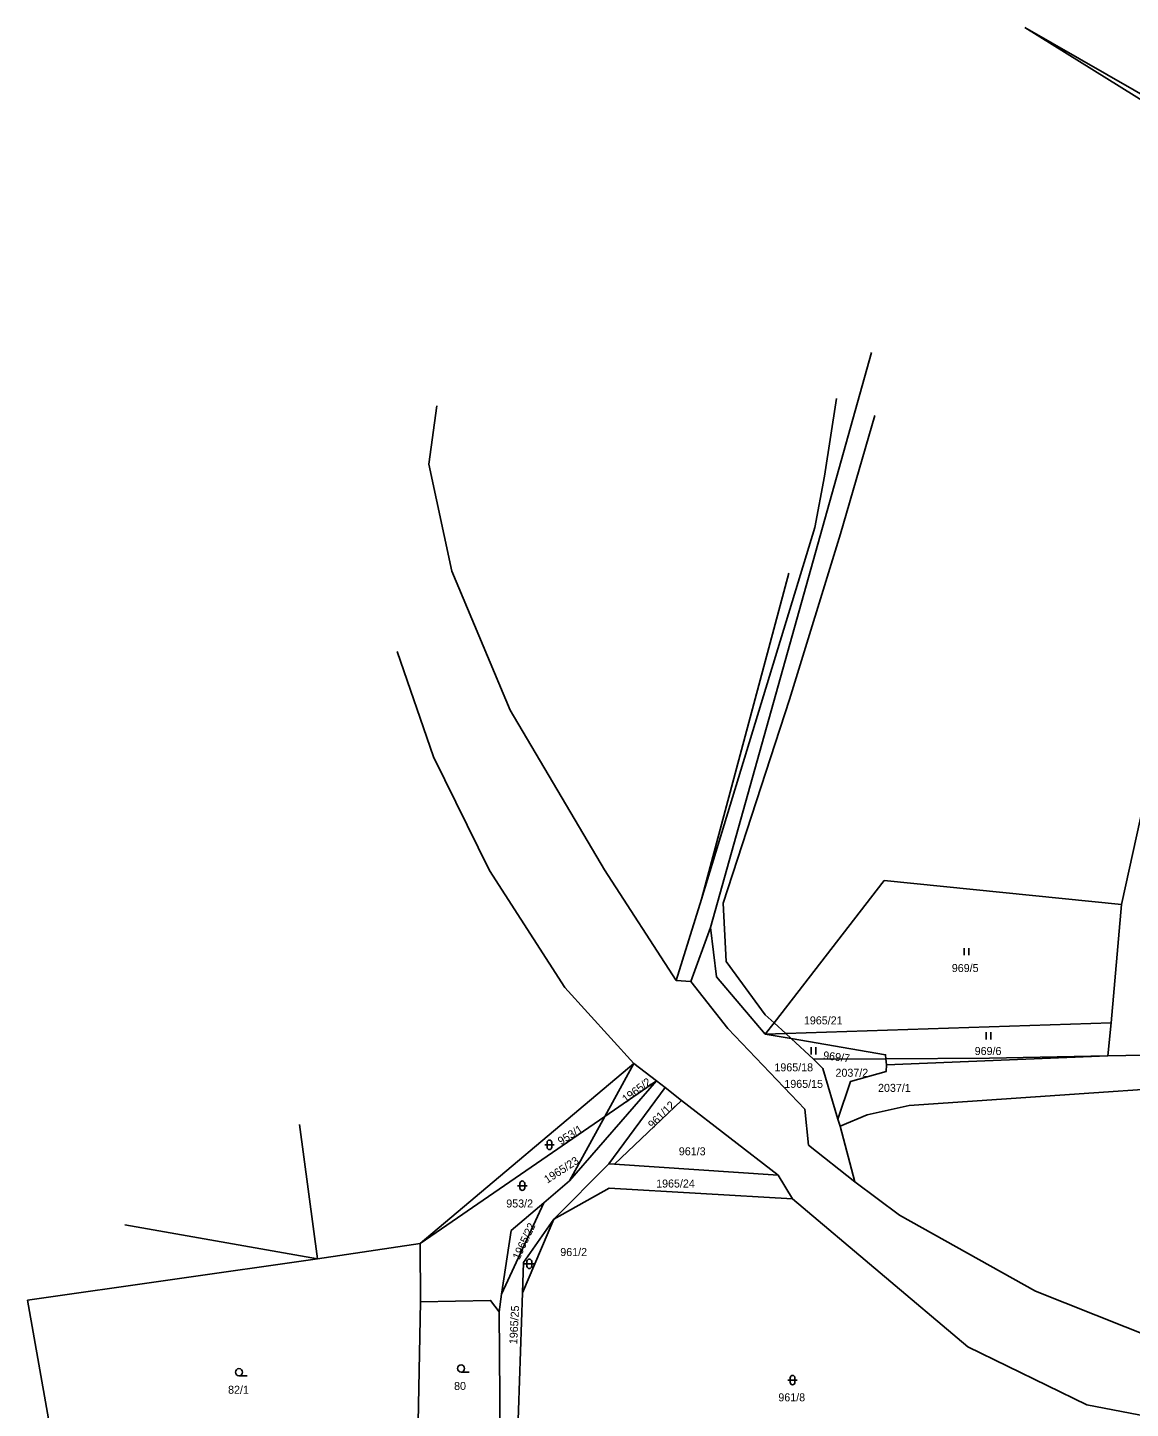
# Model space of a CAD drawing. Extents: x -794765 to -785424, y -1118958 to -1108731.
# Drawn here: x -788214.6 to -787980.3, y -1116299.9 to -1116006.6 of the extents above; entities that cross this region are included whole.
import ezdxf

# ---------------------------------------------------------------- set-up
doc = ezdxf.new("R2010")
doc.units = 0
for name, color, linetype in [('Level 66', 7, 'Continuous'), ('Level 75', 7, 'Continuous'), ('Level 76', 7, 'Continuous')]:
    doc.layers.add(name, color=color, linetype=linetype)

msp = doc.modelspace()

# ---------------------------------------------------------------- linework, layer by layer
at = {"layer": 'Level 66'}
for p, q in [((-788015.63, -1116203.58), (-788015.63, -1116202.08)), ((-788014.63, -1116203.58), (-788014.63, -1116202.08)), ((-788010.9, -1116221.48), (-788010.9, -1116219.98)), ((-788009.9, -1116221.48), (-788009.9, -1116219.98)), ((-788048.11, -1116224.67), (-788048.11, -1116223.17)), ((-788047.11, -1116224.67), (-788047.11, -1116223.17)), ((-788104.72, -1116243.88), (-788102.72, -1116243.88)), ((-788104.22, -1116243.38), (-788104.22, -1116244.38)), ((-788103.22, -1116244.38), (-788103.22, -1116243.38)), ((-788110.49, -1116252.56), (-788108.49, -1116252.56)), ((-788109.99, -1116252.06), (-788109.99, -1116253.06)), ((-788108.99, -1116253.06), (-788108.99, -1116252.06)), ((-788109, -1116269.16), (-788107, -1116269.16)), ((-788108.5, -1116268.66), (-788108.5, -1116269.66)), ((-788107.5, -1116269.66), (-788107.5, -1116268.66)), ((-788122.51, -1116292.13), (-788120.76, -1116292.13)), ((-788169.7, -1116292.92), (-788167.95, -1116292.92)), ((-788053.07, -1116293.84), (-788051.07, -1116293.84)), ((-788052.57, -1116293.34), (-788052.57, -1116294.34)), ((-788051.57, -1116294.34), (-788051.57, -1116293.34))]:
    msp.add_line(p, q, dxfattribs=at)
for centre in [(-788169.7, -1116292.17), (-788122.51, -1116291.38)]:
    msp.add_circle(centre, 0.75, dxfattribs=at)
for centre, start, end in [((-788103.72, -1116243.38), 0, 180), ((-788103.72, -1116244.38), 180, 359.9879), ((-788109.49, -1116252.06), 0, 180), ((-788109.49, -1116253.06), 180, 359.9879), ((-788108, -1116268.66), 0, 180), ((-788108, -1116269.66), 180, 359.9879), ((-788052.07, -1116293.34), 0, 180), ((-788052.07, -1116294.34), 180, 359.9879)]:
    msp.add_arc(centre, 0.5, start, end, dxfattribs=at)
at = {"layer": 'Level 75'}
for p, q in [((-788002.71, -1116006.59), (-787882.08, -1116075.64)), ((-788002.71, -1116006.59), (-787888.56, -1116077.57)), ((-788035.27, -1116075.57), (-788069.53, -1116197.7)), ((-788052.85, -1116122.43), (-788071.41, -1116191.68)), ((-788076.78, -1116209), (-788071.41, -1116191.68)), ((-787982.18, -1116192.85), (-787984.36, -1116217.96)), ((-788069.53, -1116197.7), (-788073.71, -1116209.17)), ((-788073.71, -1116209.17), (-788076.78, -1116209)), ((-788057.85, -1116220.39), (-788055.99, -1116217.98)), ((-788055.99, -1116217.98), (-788053.51, -1116220.25)), ((-788053.51, -1116220.25), (-787984.36, -1116217.96)), ((-787984.36, -1116217.96), (-787985.07, -1116224.98)), ((-788053.51, -1116220.25), (-788057.85, -1116220.39)), ((-788052.33, -1116221.33), (-788057.85, -1116220.39)), ((-788053.51, -1116220.25), (-788052.33, -1116221.33)), ((-788052.33, -1116221.33), (-788047.6, -1116225.66)), ((-788032.12, -1116226.88), (-787985.07, -1116224.98)), ((-787985.07, -1116224.98), (-787960.83, -1116224.48)), ((-788131.17, -1116264.83), (-788085.81, -1116226.64)), ((-788085.81, -1116226.64), (-788091.96, -1116237.85)), ((-788080.98, -1116230.3), (-788085.81, -1116226.64)), ((-788047.6, -1116225.66), (-788032.22, -1116225.59)), ((-788032.22, -1116225.59), (-788032.12, -1116226.88)), ((-788099.45, -1116251.52), (-788080.98, -1116230.3)), ((-788091.96, -1116237.85), (-788080.98, -1116230.3)), ((-788080.98, -1116230.3), (-788079.1, -1116231.73)), ((-788079.1, -1116231.73), (-788091.13, -1116247.9)), ((-788079.1, -1116231.73), (-788075.63, -1116234.43)), ((-788075.63, -1116234.43), (-788089.89, -1116247.98)), ((-788055.15, -1116250.34), (-788075.63, -1116234.43)), ((-788153.05, -1116268.07), (-788156.81, -1116239.54)), ((-788131.17, -1116264.83), (-788091.96, -1116237.85)), ((-788099.45, -1116251.52), (-788091.96, -1116237.85)), ((-788041.98, -1116239.94), (-788042.43, -1116238.43)), ((-788041.98, -1116239.94), (-788038.84, -1116251.72)), ((-788102.81, -1116259.69), (-788091.13, -1116247.9)), ((-788091.13, -1116247.9), (-788089.89, -1116247.98)), ((-788089.89, -1116247.98), (-788055.15, -1116250.34)), ((-788104.94, -1116256.19), (-788099.45, -1116251.52)), ((-788055.15, -1116250.34), (-788052.1, -1116255.33)), ((-788113.88, -1116275.59), (-788104.94, -1116256.19)), ((-788109.43, -1116275.32), (-788102.81, -1116259.69)), ((-788193.99, -1116260.86), (-788153.05, -1116268.07)), ((-788153.05, -1116268.07), (-788131.17, -1116264.83)), ((-788131.17, -1116264.83), (-788131.16, -1116277.26)), ((-788153.05, -1116268.07), (-788214.62, -1116276.87)), ((-788214.62, -1116276.87), (-788207.41, -1116317.68)), ((-788131.16, -1116277.26), (-788131.71, -1116307.69)), ((-788114.43, -1116279.33), (-788113.88, -1116275.59)), ((-788109.43, -1116275.32), (-788110.98, -1116320.69)), ((-788114.43, -1116279.33), (-788114.17, -1116310.48))]:
    msp.add_line(p, q, dxfattribs=at)
for points in [[(-788076.78, -1116209), (-788092, -1116185.5), (-788112.04, -1116151.55), (-788124.45, -1116122.06), (-788129.39, -1116099.34), (-788127.68, -1116086.93)], [(-788071.41, -1116191.68), (-788047.32, -1116112.79), (-788045.26, -1116101.88), (-788042.7, -1116085.39)], [(-788034.6, -1116088.94), (-788041.84, -1116114.12), (-788052.73, -1116149.32), (-788066.81, -1116192.53), (-788066.19, -1116204.97), (-788057.87, -1116216.25), (-788055.99, -1116217.98)], [(-788136.07, -1116139.09), (-788128.33, -1116161.49), (-788116.43, -1116185.63), (-788100.46, -1116210.48), (-788085.81, -1116226.64)], [(-787961.82, -1116139.28), (-787975, -1116160.37), (-787982.18, -1116192.85)], [(-787982.18, -1116192.85), (-788032.59, -1116187.72), (-788055.99, -1116217.98)], [(-788057.85, -1116220.39), (-788068.21, -1116208.21), (-788069.53, -1116197.7)], [(-788038.84, -1116251.72), (-788048.68, -1116243.92), (-788049.47, -1116236.31), (-788065.84, -1116219.2), (-788073.71, -1116209.17)], [(-788052.33, -1116221.33), (-788032.28, -1116224.75), (-788032.22, -1116225.59)], [(-788032.22, -1116225.59), (-788010.21, -1116225.5), (-787985.07, -1116224.98)], [(-788042.43, -1116238.43), (-788045.64, -1116227.68), (-788047.6, -1116225.66)], [(-788042.43, -1116238.43), (-788039.74, -1116230.4), (-788032.19, -1116228.31), (-788032.12, -1116226.88)], [(-787888.24, -1116227.49), (-787936.38, -1116229.33), (-788027.3, -1116235.54), (-788036.22, -1116237.52), (-788041.98, -1116239.94)], [(-788052.1, -1116255.33), (-788091.02, -1116253.11), (-788102.81, -1116259.69)], [(-787853.4, -1116319.28), (-787937.67, -1116297.07), (-787968.58, -1116287.61), (-788000.45, -1116274.98), (-788029.34, -1116258.85), (-788038.84, -1116251.72)], [(-788113.88, -1116275.59), (-788111.89, -1116262.1), (-788104.94, -1116256.19)], [(-788052.1, -1116255.33), (-788014.79, -1116286.8), (-787989.53, -1116299.12), (-787922.43, -1116312.01), (-787895.37, -1116318.13)], [(-788102.81, -1116259.69), (-788109.21, -1116268.89), (-788109.43, -1116275.32)], [(-788131.16, -1116277.26), (-788116.23, -1116276.92), (-788114.43, -1116279.33)]]:
    msp.add_lwpolyline(points, dxfattribs=at)

# ---------------------------------------------------------------- texts
at = {"layer": 'Level 76'}
for s, p in [('969/5', (-788018.22, -1116207.18)), ('1965/21', (-788049.65, -1116218.3)), ('969/6', (-788013.36, -1116224.8)), ('1965/18', (-788055.92, -1116228.27)), ('2037/2', (-788042.94, -1116229.42)), ('1965/15', (-788053.81, -1116231.78)), ('2037/1', (-788033.9, -1116232.63)), ('961/3', (-788076.23, -1116246.1)), ('1965/24', (-788081.05, -1116252.95)), ('953/2', (-788112.9, -1116257.19)), ('961/2', (-788101.42, -1116267.5)), ('82/1', (-788172.02, -1116296.75)), ('80', (-788123.99, -1116295.95)), ('961/8', (-788055.08, -1116298.36))]:
    msp.add_text(s, height=1.7, dxfattribs=at).set_placement(p)
for s, rotation, p in [('969/7', 353, (-788045.64, -1116225.68)), ('1965/2', 37, (-788087.49, -1116235.06)), ('961/12', 45, (-788081.78, -1116240.52)), ('953/1', 32, (-788101.3, -1116244)), ('1965/23', 33, (-788104.18, -1116252.15)), ('1965/22', 65, (-788110.11, -1116268.41)), ('1965/25', 87, (-788110.58, -1116286.26))]:
    msp.add_text(s, height=1.7, rotation=rotation, dxfattribs=at).set_placement(p)

doc.saveas('drawing.dxf')
